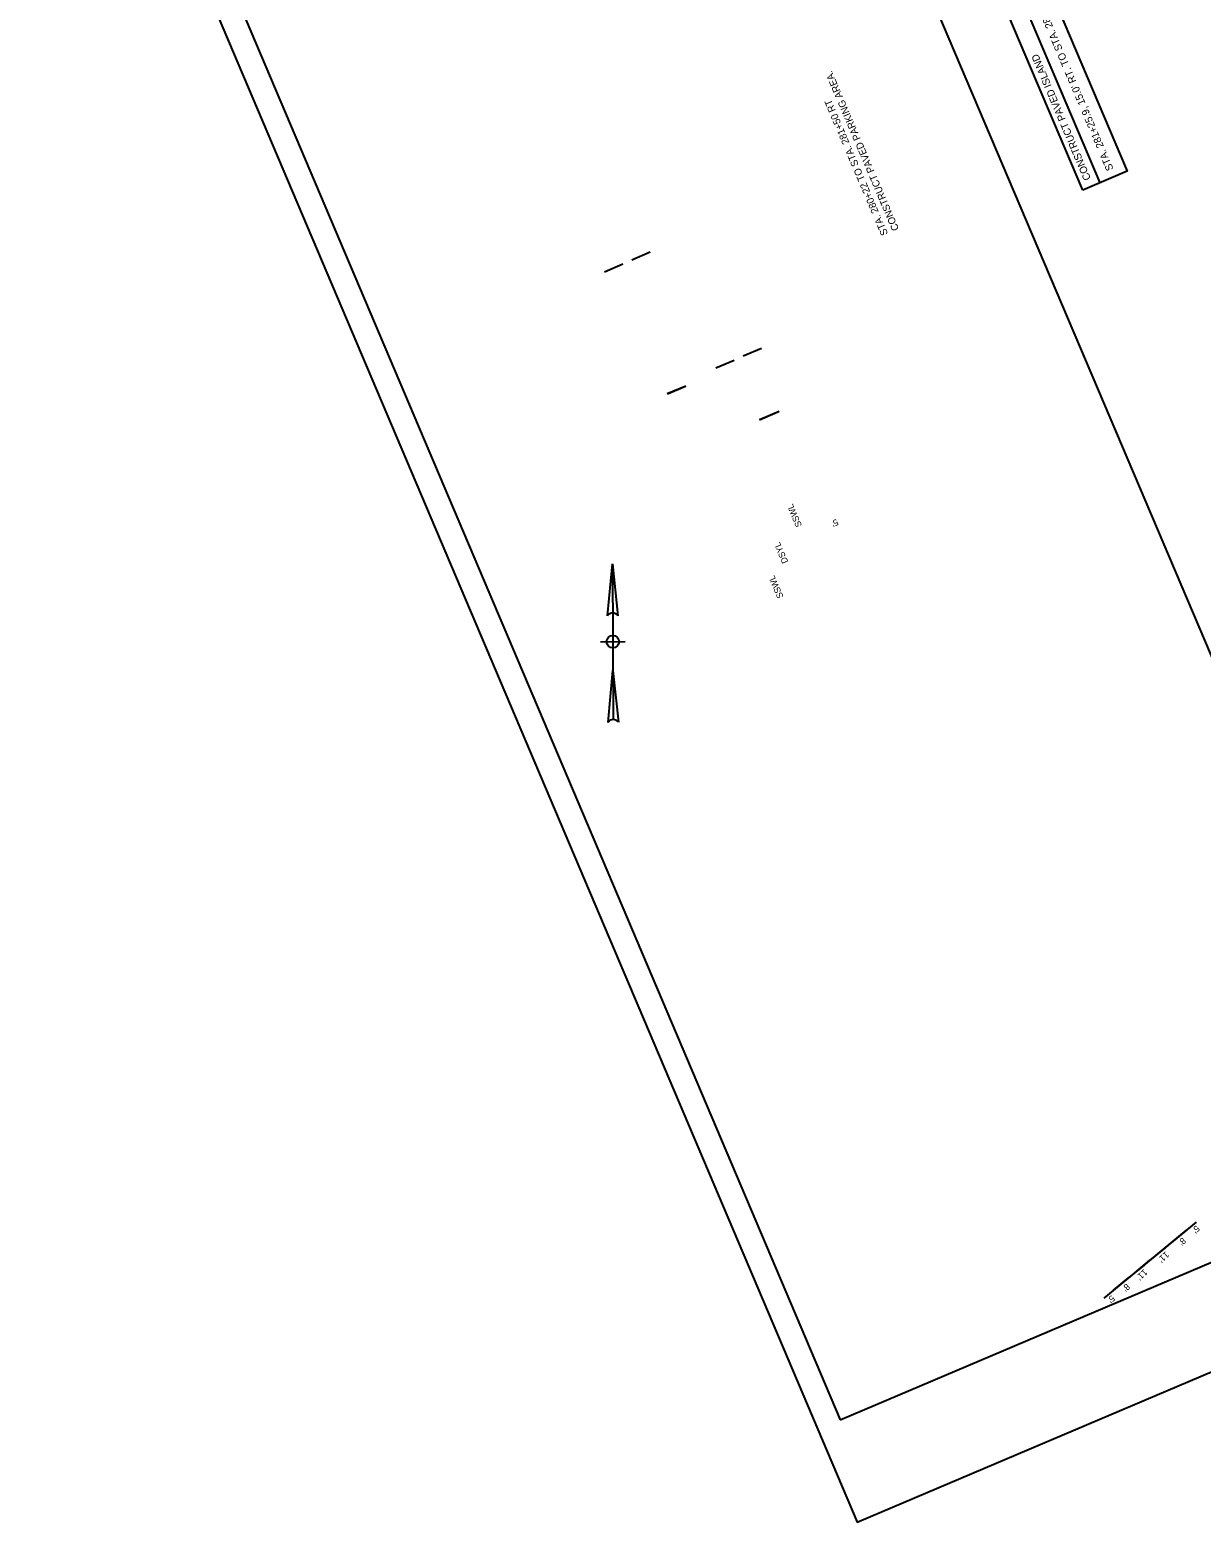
# Model space of a CAD drawing. Extents: x 1111260 to 1112098, y 617053 to 618050.
# Drawn here: x 1111260 to 1111730, y 617053 to 617652 of the extents above; entities that cross this region are included whole.
import ezdxf

# ---------------------------------------------------------------- set-up
doc = ezdxf.new("R2010")
doc.units = 0
for name, color, linetype in [('D_Roadway_Centerline_Text', 7, 'Continuous'), ('MINOR', 7, 'Continuous'), ('S_Roadway_Sidewalks_Paved', 7, 'Continuous'), ('S_Utilities_GuyWire3', 7, 'Continuous')]:
    doc.layers.add(name, color=color, linetype=linetype)

msp = doc.modelspace()

# ---------------------------------------------------------------- linework, layer by layer
at = {"layer": 'D_Roadway_Centerline_Text'}
for p, q in [((1111491.45, 617416.96), (1111493.43, 617437.8)), ((1111493.43, 617437.8), (1111493.74, 617375.3)), ((1111493.43, 617437.8), (1111495.61, 617416.98)), ((1111488.58, 617406.53), (1111498.58, 617406.58)), ((1111491.66, 617374.18), (1111493.64, 617395.02)), ((1111493.64, 617395.02), (1111495.83, 617374.2))]:
    msp.add_line(p, q, dxfattribs=at)
msp.add_circle((1111493.58, 617406.55), 2.5, dxfattribs=at)
for centre in [(1111493.54, 617415.59), (1111493.75, 617372.8)]:
    msp.add_arc(centre, 2.5, 33.84066, 146.72604, dxfattribs=at)
at = {"layer": 'MINOR'}
for p, q in [((1111821.4, 617194.62), (1111528.35, 617884.99)), ((1111272.25, 617830.6), (1111584.83, 617094.2)), ((1111584.83, 617094.2), (1112068.1, 617299.33))]:
    msp.add_line(p, q, dxfattribs=at)
at = {"layer": 'S_Roadway_Sidewalks_Paved'}
msp.add_lwpolyline([(1112097.99, 617268.06), (1111765.87, 618050.49), (1111259.59, 617835.59), (1111591.71, 617053.16)], close=True, dxfattribs=at)
at = {"layer": 'S_Utilities_GuyWire3'}
for p, q in [((1111689.19, 617590.79), (1111629.68, 617730.98)), ((1111490.24, 617555.05), (1111497.59, 617558.18)), ((1111508.64, 617562.86), (1111501.27, 617559.75)), ((1111553.32, 617524.28), (1111545.95, 617521.17)), ((1111534.93, 617516.47), (1111542.28, 617519.6)), ((1111522.83, 617509.13), (1111515.46, 617506.01)), ((1111515.47, 617506.01), (1111522.82, 617509.14)), ((1111560.37, 617498.99), (1111552.48, 617495.65)), ((1111552.48, 617495.64), (1111559.83, 617498.77)), ((1111723.81, 617170.29), (1111717.69, 617165.27)), ((1111717.69, 617165.27), (1111723.81, 617170.29)), ((1111715.3, 617163.32), (1111709.18, 617158.29)), ((1111711.56, 617160.25), (1111717.69, 617165.27)), ((1111703.06, 617153.27), (1111709.18, 617158.29)), ((1111700.61, 617151.27), (1111694.49, 617146.25)), ((1111694.55, 617146.3), (1111700.68, 617151.32)), ((1111706.8, 617156.34), (1111700.68, 617151.32))]:
    msp.add_line(p, q, dxfattribs=at)
msp.add_lwpolyline([(1111682.21, 617587.83), (1111622.71, 617728.02), (1111640.55, 617735.59), (1111700.05, 617595.4)], close=True, dxfattribs=at)
msp.add_lwpolyline([(1111727.74, 617173.52), (1111690.62, 617143.07)], dxfattribs=at)

# ---------------------------------------------------------------- texts
for s, height, rotation, p in [("STA. 281+25.9, 15.0' RT. TO STA. 281+50.2, 27.4' RT.", 2.9531, 113, (1111694.61, 617596.29)), ('CONSTRUCT PAVED ISLAND', 2.9531, 113, (1111685.55, 617592.45)), ('CONSTRUCT PAVED PARKING AREA.', 2.88, 113, (1111608.53, 617572.17)), ('STA. 280+22 TO STA. 281+50 RT', 2.88, 113, (1111604.11, 617570.3)), ('SSWL', 2.55, 113.39459, (1111569.57, 617453.21)), ("5'", 2.55, 206.13207, (1111583.33, 617455.92)), ('DSYL', 2.55, 113.39459, (1111564.06, 617438.6)), ('SSWL', 2.55, 113.39459, (1111562.17, 617424.58)), ("5'", 2.55, 222.54781, (1111727.75, 617172.48)), ("8'", 2.55, 222.54781, (1111722.22, 617167.57)), ("11'", 2.55, 222.54781, (1111715.48, 617161.98)), ("11'", 2.55, 222.54781, (1111706.81, 617154.89)), ("8'", 2.55, 222.54781, (1111699.71, 617149.12)), ("5'", 2.55, 222.54781, (1111693.73, 617144.46))]:
    msp.add_text(s, height=height, rotation=rotation, dxfattribs=at).set_placement(p)

doc.saveas('drawing.dxf')
